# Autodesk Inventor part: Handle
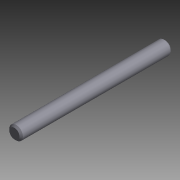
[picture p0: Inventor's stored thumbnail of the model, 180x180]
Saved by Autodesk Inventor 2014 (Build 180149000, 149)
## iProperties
Shininess: 0.0
Length Units: 11272
Angle Units: 11279
Time Units: 11290
Mass Units: 11283
Length Display Precision: 2
Angle Display Precision: 1
Compacted: True
Created: 1999-05
Part Number: Handle
Document SubType Name: Modeling
Designer: Administrator
Density: 7.86 g/cm^3
Material: Steel, Mild
Mass: 17.0368 g
Surface Area: 14.2531 cm^2
Volume: 2.16753 cm^3
Appearance: Metal - Steel 2
Density: 0.0
Volumn: 0.0
Area: 0.0
PropertySet Name: Model Information
Control State: 0
Master: False
Checked Out: False
Author: Administrator
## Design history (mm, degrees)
node "y-z Plane"
  node "x-z Plane"
  node "x-y Plane"
node "Extrusion1" dims "d1" = 69.85, "d2" = 0
  sketch "Sketch1"
    geometry: C1 r 3.151 at (0, 0); 1 further point
    constraints: 1 centre point, 1 coincident
    dimensions: "d0" = 6.30225 diameter of C1
node "Chamfer1" dims "d3" = 0.79375, "d4" = 0.79375, "d5" = 45 deg
body "Solid1"
